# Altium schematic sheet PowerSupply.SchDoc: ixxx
size A4; Organization: Ingenia Motion Control; Address1: Barcelona Advanced Industry Park; Address2: C/Marie Curie 8-14 08042 Barcelona Spain; Address3: www.ingeniamc.com; Address4: www.ingeniamc.com; Revision: 1.0.0
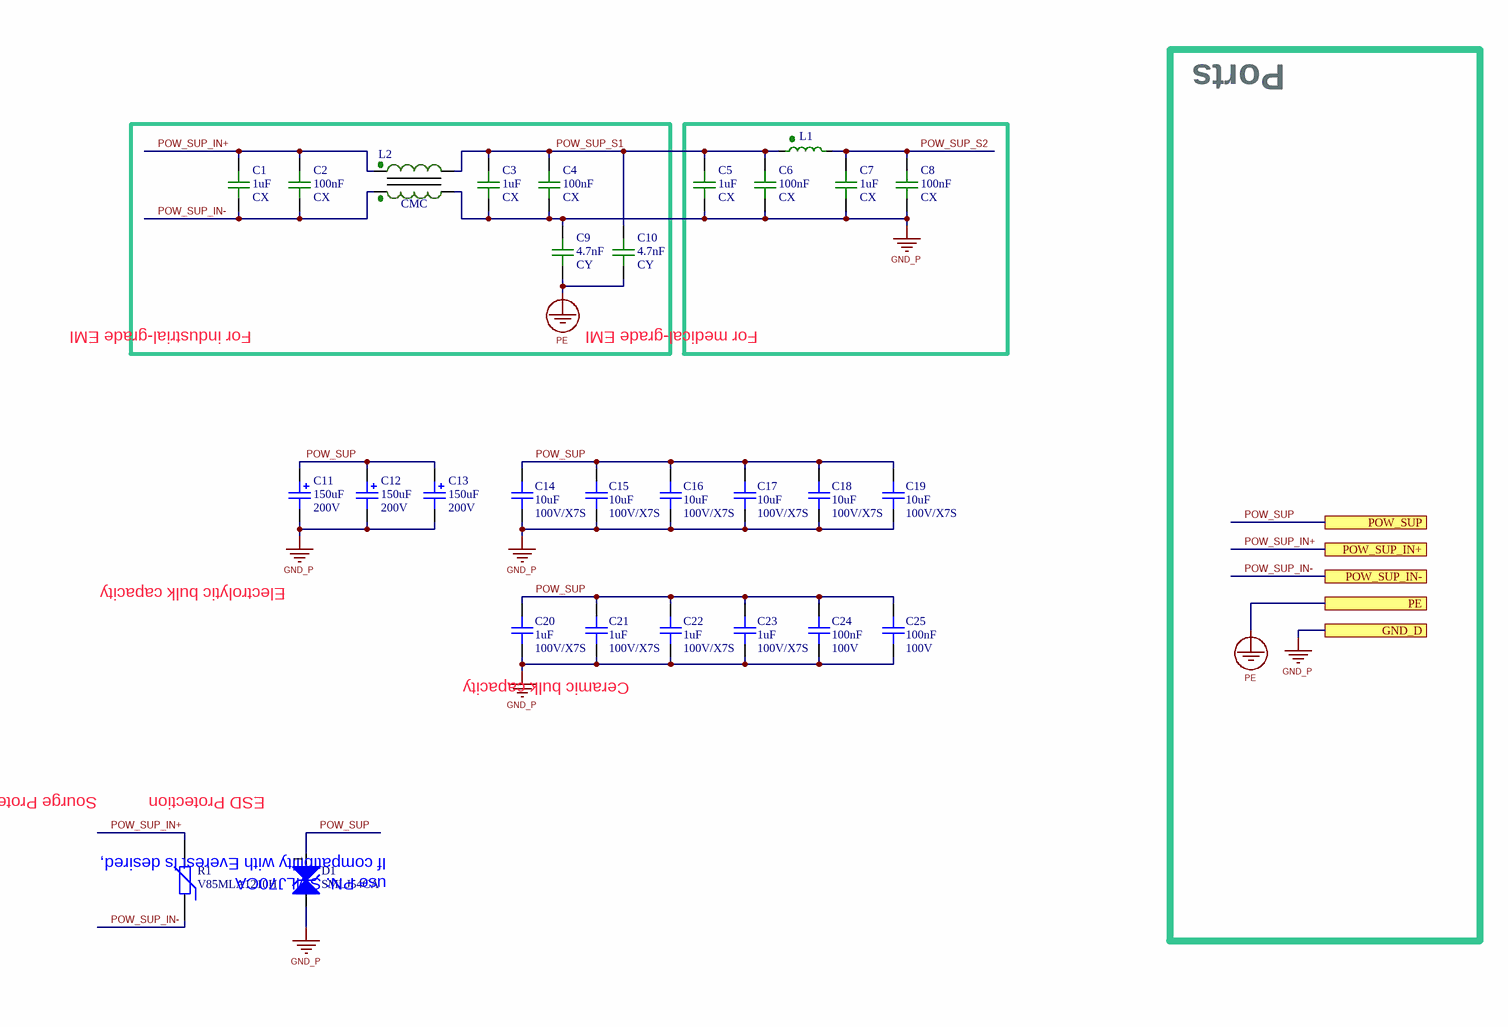
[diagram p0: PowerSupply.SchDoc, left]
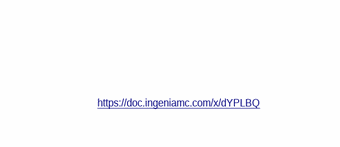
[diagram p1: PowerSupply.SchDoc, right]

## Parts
C1  value 1uF  Voltage: CX  [C_0402]  (hidden comment: C_0402)
C2  value 100nF  Voltage: CX  [C_0402]  (hidden comment: C_0402)
C3  value 1uF  Voltage: CX  [C_0402]  (hidden comment: C_0402)
C4  value 100nF  Voltage: CX  [C_0402]  (hidden comment: C_0402)
C5  value 1uF  Voltage: CX  [C_0402]  (hidden comment: C_0402)
C6  value 100nF  Voltage: CX  [C_0402]  (hidden comment: C_0402)
C7  value 1uF  Voltage: CX  [C_0402]  (hidden comment: C_0402)
C8  value 100nF  Voltage: CX  [C_0402]  (hidden comment: C_0402)
C9  value 4.7nF  Voltage: CY  [C_0402]  (hidden comment: C_0402)
C10  value 4.7nF  Voltage: CY  [C_0402]  (hidden comment: C_0402)
C11  value 150uF  Voltage: 200V  [C_16x25]  (hidden comment: EKXG201ELL151ML25S--150uF--200V)
C12  value 150uF  Voltage: 200V  [C_16x25]  (hidden comment: EKXG201ELL151ML25S--150uF--200V)
C13  value 150uF  Voltage: 200V  [C_16x25]  (hidden comment: EKXG201ELL151ML25S--150uF--200V)
C14  value 10uF  Voltage: 100V/X7S  [C_2220]  (hidden comment: C_2220--10uF--100V/X7S)
C15  value 10uF  Voltage: 100V/X7S  [C_2220]  (hidden comment: C_2220--10uF--100V/X7S)
C16  value 10uF  Voltage: 100V/X7S  [C_2220]  (hidden comment: C_2220--10uF--100V/X7S)
C17  value 10uF  Voltage: 100V/X7S  [C_2220]  (hidden comment: C_2220--10uF--100V/X7S)
C18  value 10uF  Voltage: 100V/X7S  [C_2220]  (hidden comment: C_2220--10uF--100V/X7S)
C19  value 10uF  Voltage: 100V/X7S  [C_2220]  (hidden comment: C_2220--10uF--100V/X7S)
C20  value 1uF  Voltage: 100V/X7S  [C_0805_HV]  (hidden comment: C_0805--1uF--100V/X7S)
C21  value 1uF  Voltage: 100V/X7S  [C_0805_HV]  (hidden comment: C_0805--1uF--100V/X7S)
C22  value 1uF  Voltage: 100V/X7S  [C_0805_HV]  (hidden comment: C_0805--1uF--100V/X7S)
C23  value 1uF  Voltage: 100V/X7S  [C_0805_HV]  (hidden comment: C_0805--1uF--100V/X7S)
C24  value 100nF  Voltage: 100V  [C_0805]  (hidden comment: C_0805--100nF--100V)
C25  value 100nF  Voltage: 100V  [C_0805]  (hidden comment: C_0805--100nF--100V)
D1  SMLJ54CA  [SMC/DO-214-AB]
L1  L_VIRTUAL  (value not drawn)
L2  CMC  (no BOM)
R1  V85MLA1210H  [R_1210]

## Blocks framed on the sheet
For industrial-grade EMI: C1-C4 C9 C10 L2
For medical-grade EMI: C5-C8 L1

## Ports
GND_D, PE, POW_SUP, POW_SUP_IN+, POW_SUP_IN-

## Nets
GND_P: C3.2 C4.2 C5.2 C6.2 C7.2 C8.2 C9.1 C11.2 C12.2 C13.2 C14.2 C15.2 C16.2 C17.2 C18.2 C19.2 C20.2 C21.2 C22.2 C23.2 C24.2 C25.2 D1.2 L2.9 ; port GND_D
PE: C9.2 C10.2 ; port PE
POW_SUP: C11.1 C12.1 C13.1 C14.1 C15.1 C16.1 C17.1 C18.1 C19.1 C20.1 C21.1 C22.1 C23.1 C24.1 C25.1 D1.1 ; port POW_SUP
POW_SUP_IN+: C1.1 C2.1 L2.4 R1.2 ; port POW_SUP_IN+
POW_SUP_IN-: C1.2 C2.2 L2.2 R1.1 ; port POW_SUP_IN-
POW_SUP_S1: C3.1 C4.1 C5.1 C6.1 C10.1 L1.1 L2.7
POW_SUP_S2: C7.1 C8.1 L1.2

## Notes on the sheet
- Ports
- (near C20) Electrolytic bulk capacity
- Ceramic bulk capacity
- Sourge Protection
- ESD Protection
- If compatibility with Everest is desired,
- use PN: SMLJ70CA
- https://doc.ingeniamc.com/x/dYPLBQ

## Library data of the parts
C1-C10 = C_0402[[/\]]TBD[[/\]]TBD: VIRTUAL COMPONENT!; CompletePN: C_0402--TBD--TBD; IsPreferred: 0; IsGeneric: 1
C11-C13 = EKXG201ELL151ML25S[[/\]]150uF[[/\]]200V: CAP ALUM 150UF 20% 200V RADIAL; ManufacturerName: United Chemi-Con; IsPreferred: 0; IngeniaID: 4343; TemperatureMaxC: 105; TemperatureMinC: -40
C14-C19 = C_2220[[/\]]10uF[[/\]]100V/X7S: Ceramic Capacitor MLCC 10uF 100V X7S 10%; ManufacturerName: TDK; ManufacturerPN: C5750X7S2A106K230KB; IsPreferred: 0; IsGeneric: 1; IngeniaID: 2931; AdditionalInformation: 2nd alternative. CGA9N3X7S2A106K230KE (TDK); AlternativePN: CGA9N3X7S2A106M230KE; TemperatureMaxC: 125; TemperatureMinC: -55
C20-C23 = C_0805[[/\]]1uF[[/\]]100V/X7S: MLCC, 1uF 100V X7S Boardflex 1.45mm height; Part Number: C_0805; ManufacturerName: TDK Corporation; ManufacturerPN: C2012X7S2A105K125AE; IsPreferred: 1; IngeniaID: 2972; InternalStock: 0; AlternativePN: C2012X7S2A105M125AE; MTBF55h: 28045508; TemperatureMaxC: 125; TemperatureMinC: -55
C24 C25 = C_0805[[/\]]100nF[[/\]]100V: CAP CER 100nF 100V X7R 0805; ManufacturerName: Taiyo yuden; ManufacturerPN: HMK212B7104KG-T; AlternativeManufacturer: AVX; IsPreferred: 0; IsGeneric: 1; IngeniaID: 399; AlternativePN: 08051C104K4Z2A; TemperatureMaxC: 125; TemperatureMinC: -55
D1 = SMLJ54CA: DIODE TVS 54V 3000W Bidirectional SMD; ManufacturerName: Bourns; Value: TVS 54V; IsPreferred: 0; IngeniaID: 5274
L1 = L_VIRTUAL[[/\]]TBD: Virtual component, inductor; Value: TBD; CompletePN: L_VIRTUAL--TBD; IsPreferred: 0
L2 = CMC_TBD[[/\]]TBD: Virtual component, Common Mode Choke; ManufacturerName: Ingenia; AlternativeManufacturer: Stackpole; Value: TBD; CompletePN: CMC_TBD--TBD; IsPreferred: 0; IngeniaID: 4546; AlternativePN: RMCF0402ZT0R00
R1 = V85MLA1210H: Varistor, 85V, 1210; ManufacturerName: Littelfuse; IsPreferred: 1; IsGeneric: 0; IngeniaID: 802; TemperatureMaxC: 125; TemperatureMinC: -55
